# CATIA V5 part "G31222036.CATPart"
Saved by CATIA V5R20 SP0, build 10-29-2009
Part number: G31222036
Revision: 7
Definition: design
Nomenclature: G31222036
Source: made
Description: NOT SPECIFIED
Bounding box of the stored display mesh (mm): x -8 to 36, y -17.322 to 17.322, z -17.5 to 17.5
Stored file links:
  C:\Users\Raffaele\Desktop\3D X SITO CF\BOLEX\23-BUSH REF 312\G31222036.CATPart

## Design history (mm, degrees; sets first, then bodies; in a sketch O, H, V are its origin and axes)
Body1 "MANIFOLD_SOLID_BREP #8253" (main body)
  Solid1: solid without history
Body2 "MANIFOLD_SOLID_BREP #8402"
  Solid2: solid without history
Body3 "MANIFOLD_SOLID_BREP #8551"
  Solid3: solid without history
Body4 "MANIFOLD_SOLID_BREP #8700"
  Solid4: solid without history
Body5 "MANIFOLD_SOLID_BREP #8849"
  Solid5: solid without history
Body6 "MANIFOLD_SOLID_BREP #8998"
  Solid6: solid without history
Body7 "MANIFOLD_SOLID_BREP #9147"
  Solid7: solid without history
Body8 "MANIFOLD_SOLID_BREP #9296"
  Solid8: solid without history
Body9 "MANIFOLD_SOLID_BREP #9445"
  Solid9: solid without history
Body10 "MANIFOLD_SOLID_BREP #9594"
  Solid10: solid without history
Body11 "MANIFOLD_SOLID_BREP #9743"
  Solid11: solid without history
Body12 "MANIFOLD_SOLID_BREP #9892"
  Solid12: solid without history
Body13 "MANIFOLD_SOLID_BREP #10041"
  Solid13: solid without history
Body14 "MANIFOLD_SOLID_BREP #10190"
  Solid14: solid without history
Body15 "MANIFOLD_SOLID_BREP #10339"
  Solid15: solid without history
Body16 "MANIFOLD_SOLID_BREP #10488"
  Solid16: solid without history
Body17 "MANIFOLD_SOLID_BREP #10637"
  Solid17: solid without history
Body18 "MANIFOLD_SOLID_BREP #10786"
  Solid18: solid without history
Body19 "MANIFOLD_SOLID_BREP #10935"
  Solid19: solid without history
Body20 "MANIFOLD_SOLID_BREP #11084"
  Solid20: solid without history
Body21 "MANIFOLD_SOLID_BREP #11233"
  Solid21: solid without history
Body22 "MANIFOLD_SOLID_BREP #11382"
  Solid22: solid without history
Body23 "MANIFOLD_SOLID_BREP #11531"
  Solid23: solid without history
Body24 "MANIFOLD_SOLID_BREP #11680"
  Solid24: solid without history
Body25 "MANIFOLD_SOLID_BREP #11829"
  Solid25: solid without history
Body26 "MANIFOLD_SOLID_BREP #11978"
  Solid26: solid without history
Body27 "MANIFOLD_SOLID_BREP #12127"
  Solid27: solid without history
Body28 "MANIFOLD_SOLID_BREP #12276"
  Solid28: solid without history
Body29 "MANIFOLD_SOLID_BREP #12425"
  Solid29: solid without history
Body30 "MANIFOLD_SOLID_BREP #12574"
  Solid30: solid without history
Body31 "MANIFOLD_SOLID_BREP #12723"
  Solid31: solid without history
Body32 "MANIFOLD_SOLID_BREP #12872"
  Solid32: solid without history
Body33 "MANIFOLD_SOLID_BREP #13021"
  Solid33: solid without history
Body34 "MANIFOLD_SOLID_BREP #13170"
  Solid34: solid without history
Body35 "MANIFOLD_SOLID_BREP #13319"
  Solid35: solid without history
Body36 "MANIFOLD_SOLID_BREP #13468"
  Solid36: solid without history
Body37 "MANIFOLD_SOLID_BREP #13617"
  Solid37: solid without history
Body38 "MANIFOLD_SOLID_BREP #13766"
  Solid38: solid without history
Body39 "MANIFOLD_SOLID_BREP #13915"
  Solid39: solid without history
Body40 "MANIFOLD_SOLID_BREP #14064"
  Solid40: solid without history
Body41 "MANIFOLD_SOLID_BREP #14213"
  Solid41: solid without history
Body42 "MANIFOLD_SOLID_BREP #14362"
  Solid42: solid without history
Body43 "MANIFOLD_SOLID_BREP #14511"
  Solid43: solid without history
Body44 "MANIFOLD_SOLID_BREP #14660"
  Solid44: solid without history
Body45 "MANIFOLD_SOLID_BREP #14809"
  Solid45: solid without history
Body46 "MANIFOLD_SOLID_BREP #14958"
  Solid46: solid without history
Body47 "MANIFOLD_SOLID_BREP #15107"
  Solid47: solid without history
Body48 "MANIFOLD_SOLID_BREP #15256"
  Solid48: solid without history
Body49 "MANIFOLD_SOLID_BREP #15405"
  Solid49: solid without history
Body50 "MANIFOLD_SOLID_BREP #15554"
  Solid50: solid without history
Body51 "MANIFOLD_SOLID_BREP #15703"
  Solid51: solid without history
Body52 "MANIFOLD_SOLID_BREP #15852"
  Solid52: solid without history
Body53 "MANIFOLD_SOLID_BREP #16001"
  Solid53: solid without history
Body54 "MANIFOLD_SOLID_BREP #16150"
  Solid54: solid without history
Body55 "MANIFOLD_SOLID_BREP #16299"
  Solid55: solid without history
Body56 "MANIFOLD_SOLID_BREP #16448"
  Solid56: solid without history
Body57 "MANIFOLD_SOLID_BREP #16597"
  Solid57: solid without history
